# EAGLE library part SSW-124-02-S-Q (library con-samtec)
THROUGH-HOLE .025" SQ POST SOCKET Source: Samtec SSW.pdf
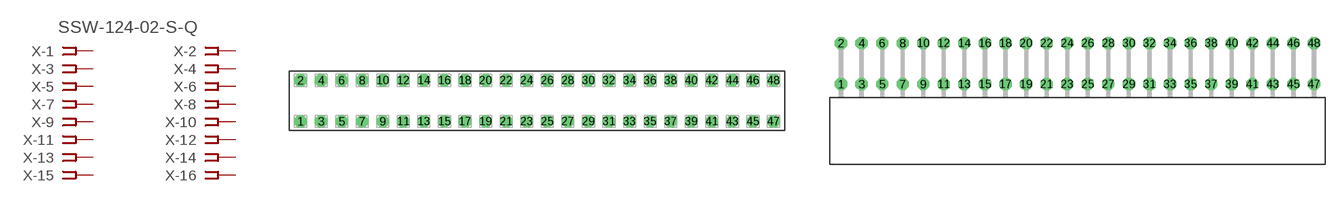
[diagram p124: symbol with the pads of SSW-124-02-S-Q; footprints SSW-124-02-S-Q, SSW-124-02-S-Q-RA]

Designator prefix X; gates -1=FPINV -2=FPIN -3=FPIN -4=FPIN -5=FPIN -6=FPIN -7=FPIN -8=FPIN -9=FPIN -10=FPIN -11=FPIN -12=FPIN -13=FPIN -14=FPIN -15=FPIN -16=FPIN -17=FPIN -18=FPIN -19=FPIN -20=FPIN -21=FPIN -22=FPIN -23=FPIN -24=FPIN -25=FPIN -26=FPIN -27=FPIN -28=FPIN -29=FPIN -30=FPIN -31=FPIN -32=FPIN -33=FPIN -34=FPIN -35=FPIN -36=FPIN -37=FPIN -38=FPIN -39=FPIN -40=FPIN -41=FPIN -42=FPIN -43=FPIN -44=FPIN -45=FPIN -46=FPIN -47=FPIN -48=FPIN

## SSW-124-02-S-Q (MPN: SSW-124-02-S-Q; OC_FARNELL: unknown; OC_NEWARK: 82P9054)  [SSW-124-02-S-Q]
1  -1:1  pas
2  -2:1  pas
3  -3:1  pas
4  -4:1  pas
5  -5:1  pas
6  -6:1  pas
7  -7:1  pas
8  -8:1  pas
9  -9:1  pas
10  -10:1  pas
11  -11:1  pas
12  -12:1  pas
13  -13:1  pas
14  -14:1  pas
15  -15:1  pas
16  -16:1  pas
17  -17:1  pas
18  -18:1  pas
19  -19:1  pas
20  -20:1  pas
21  -21:1  pas
22  -22:1  pas
23  -23:1  pas
24  -24:1  pas
25  -25:1  pas
26  -26:1  pas
27  -27:1  pas
28  -28:1  pas
29  -29:1  pas
30  -30:1  pas
31  -31:1  pas
32  -32:1  pas
33  -33:1  pas
34  -34:1  pas
35  -35:1  pas
36  -36:1  pas
37  -37:1  pas
38  -38:1  pas
39  -39:1  pas
40  -40:1  pas
41  -41:1  pas
42  -42:1  pas
43  -43:1  pas
44  -44:1  pas
45  -45:1  pas
46  -46:1  pas
47  -47:1  pas
48  -48:1  pas

## SSW-124-02-S-QRA (MPN: SSW-124-02-S-Q-RA; OC_FARNELL: unknown; OC_NEWARK: 82P9055)  [SSW-124-02-S-Q-RA]
Pads as for SSW-124-02-S-Q

## Footprint SSW-124-02-S-Q (pad centres in mm)
THROUGH-HOLE .025" SQ POST SOCKET Source: Samtec SSW.pdf
drill 1 pad 1.5 octagon: 1 -29.21,-2.54; 2 -29.21,2.54; 3 -26.67,-2.54; 4 -26.67,2.54; 5 -24.13,-2.54; 6 -24.13,2.54; 7 -21.59,-2.54; 8 -21.59,2.54; 9 -19.05,-2.54; 10 -19.05,2.54; 11 -16.51,-2.54; 12 -16.51,2.54; 13 -13.97,-2.54; 14 -13.97,2.54; 15 -11.43,-2.54; 16 -11.43,2.54; 17 -8.89,-2.54; 18 -8.89,2.54; 19 -6.35,-2.54; 20 -6.35,2.54; 21 -3.81,-2.54; 22 -3.81,2.54; 23 -1.27,-2.54; 24 -1.27,2.54; 25 1.27,-2.54; 26 1.27,2.54; 27 3.81,-2.54; 28 3.81,2.54; 29 6.35,-2.54; 30 6.35,2.54; 31 8.89,-2.54; 32 8.89,2.54; 33 11.43,-2.54; 34 11.43,2.54; 35 13.97,-2.54; 36 13.97,2.54; 37 16.51,-2.54; 38 16.51,2.54; 39 19.05,-2.54; 40 19.05,2.54; 41 21.59,-2.54; 42 21.59,2.54; 43 24.13,-2.54; 44 24.13,2.54; 45 26.67,-2.54; 46 26.67,2.54; 47 29.21,-2.54; 48 29.21,2.54

## Footprint SSW-124-02-S-Q-RA (pad centres in mm)
THROUGH-HOLE .025" SQ POST SOCKET Source: Samtec SSW.pdf
drill 1 pad 1.5 octagon: 1 -29.21,1.524; 2 -29.21,6.604; 3 -26.67,1.524; 4 -26.67,6.604; 5 -24.13,1.524; 6 -24.13,6.604; 7 -21.59,1.524; 8 -21.59,6.604; 9 -19.05,1.524; 10 -19.05,6.604; 11 -16.51,1.524; 12 -16.51,6.604; 13 -13.97,1.524; 14 -13.97,6.604; 15 -11.43,1.524; 16 -11.43,6.604; 17 -8.89,1.524; 18 -8.89,6.604; 19 -6.35,1.524; 20 -6.35,6.604; 21 -3.81,1.524; 22 -3.81,6.604; 23 -1.27,1.524; 24 -1.27,6.604; 25 1.27,1.524; 26 1.27,6.604; 27 3.81,1.524; 28 3.81,6.604; 29 6.35,1.524; 30 6.35,6.604; 31 8.89,1.524; 32 8.89,6.604; 33 11.43,1.524; 34 11.43,6.604; 35 13.97,1.524; 36 13.97,6.604; 37 16.51,1.524; 38 16.51,6.604; 39 19.05,1.524; 40 19.05,6.604; 41 21.59,1.524; 42 21.59,6.604; 43 24.13,1.524; 44 24.13,6.604; 45 26.67,1.524; 46 26.67,6.604; 47 29.21,1.524; 48 29.21,6.604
